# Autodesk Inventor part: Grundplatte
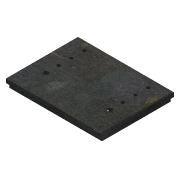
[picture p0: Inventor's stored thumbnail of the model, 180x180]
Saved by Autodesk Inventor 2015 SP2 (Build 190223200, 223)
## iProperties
Created: 2017-07
Material: St
Document SubType Name: Modeling
Designer: UR
Density: 7.85 g/cm^3
Appearance: Platte
Part Number: Grundplatte
Author: UR
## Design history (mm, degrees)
sketch "Skizze1"
  geometry: L1 (-60, 45)-(60, 45); L2 (60, 45)-(60, -45); L3 (60, -45)-(-60, -45); L4 (-60, -45)-(-60, 45); L5 (60, 45)-(-60, -45); 2 further points
  constraints: 10 end point, 2 parallel, 1 coincident, 1 horizontal, 1 midpoint, 1 perpendicular
  dimensions: "d0" = 120 distance of L2.end L3.end; "d1" = 90 distance of L3.end L1.start
extrude "Grundkörper" new body sketch "Skizze1" distance "d3" = 12; taper "d4" = 0 deg
node "Mittelebene xz"
node "Mittelebene yz"
sketch "Skizze für Bohrungen"
  geometry: L1 (0, 0)-(0, -15.692); L2 (60, 45)-(-60, 45) reference; 8 further points
  constraints: 4 symmetric about line, 3 vertical alignment, 2 end point, 1 vertical
  dimensions: "d5" = 80 distance of point (-40, -15) point (40, -15); "d6" = 16 distance of point (-40, 1) point (-40, -15); "d7" = 16 distance of point (-40, 17) point (-40, 1); "d8" = 16 distance of point (-40, 33) point (-40, 17); "d9" = 12 distance from line of point (-40, 33) L2
hole "Bohrung für Stanzmatrize" sketch "Skizze für Bohrungen" diameter "d10" = 6; stored, may be unused: countersink angle "d14" = 90 deg, drill point angle "d16" = 118 deg; dims "d11" = 6, "d12" = 4, "d13" = 2, "d15" = 8
hole "Durchgangsbohrung zur Oberplatte" sketch "Skizze für Bohrungen" diameter "d17" = 4.5; stored, may be unused: countersink angle "d21" = 90 deg, drill point angle "d23" = 118 deg; dims "d18" = 6, "d19" = 8, "d20" = 4.4, "d22" = 8
hole "Bohrung für Zylinderstifte" sketch "Skizze für Bohrungen" diameter "d24" = 4; stored, may be unused: countersink angle "d28" = 90 deg, drill point angle "d30" = 118 deg; dims "d25" = 6, "d26" = 8, "d27" = 4.4, "d29" = 8
sketch "Skizze3"
  geometry: L1 (60, 45)-(-60, 45) reference; L2 (-60, 45)-(-60, -45) reference; L3 (-60, -45)-(60, -45) reference; L4 (60, -45)-(60, 45) reference; L5 (0, 0)-(0, -20.468); L6 (-50, -40)-(50, -40); L7 (55, -35)-(55, -13); L8 (-55, -35)-(-55, -13); L9 (-26, 40)-(26, 40); L10 (-31, 35)-(-31, -8); L11 (31, 35)-(31, -8); L12 (-50, -8)-(-31, -8); L13 (31, -8)-(50, -8); C1 r 2 at (40, 17) reference; C2 r 2 at (-40, 17) reference; C3 r 4 at (-40, 33) reference; C4 r 4 at (40, 1) reference; C5 r 4 at (40, 33) reference; C6 r 4 at (-40, 1) reference; C7 r 3 at (40, -15) reference; C8 r 3 at (-40, -15) reference; A1 r 5 centre (-26, 35) between (-26, 40) and (-31, 35); A2 r 5 centre (-50, -13) between (-50, -8) and (-55, -13); A3 r 5 centre (-50, -35) between (-55, -35) and (-50, -40); A4 r 5 centre (26, 35) between (31, 35) and (26, 40); A5 r 5 centre (50, -13) between (55, -13) and (50, -8); A6 r 5 centre (50, -35) between (50, -40) and (55, -35)
  constraints: 18 end point, 12 point on circle, 9 tangent, 6 centre point, 6 perpendicular, 3 symmetric about line, 2 equal radius, 2 parallel, 2 vertical, 3 other
  dimensions: "d31" = 5 radius of A6; "d33" = 5 distance between parallel lines of L3 L6; "d34" = 5 distance between parallel lines of L9 L1; "d35" = 5 distance between parallel lines of L4 L7; "d36" = 5 distance edge to line of C3 L10; "d37" = 5 distance edge to line of C6 L12
extrude "Konfettitasche" cut sketch "Skizze3" distance "d38" = 10; taper "d39" = 0 deg
sketch "Skizze4"
  geometry: L1 (50, -40)-(-50, -40) reference; L2 (-55, -35)-(-55, -13) reference; L3 (-50, -8)-(-31, -8) reference; L4 (-31, -8)-(-31, 35) reference; L5 (-26, 40)-(26, 40) reference; L6 (31, 35)-(31, -8) reference; L7 (31, -8)-(50, -8) reference; L8 (55, -13)-(55, -35) reference; L9 (60, 45)-(-60, 45) reference; L10 (-60, 45)-(-60, -45) reference; L11 (-60, -45)-(60, -45) reference; L12 (60, -45)-(60, 45) reference; L13 (-60, 45)-(60, 45) reference; L14 (0, 45)-(0, 0); L15 (-60, -45)-(-60, 45) reference; L16 (60, 45)-(60, -45) reference; L17 (60, 0)-(-60, 0); L18 (-6, 6)-(6, 6); L19 (6, 6)-(6, -6); L20 (6, -6)-(-6, -6); L21 (-6, -6)-(-6, 6); C1 r 2 at (40, 17) reference; C2 r 2 at (-40, 17) reference; C3 r 4 at (-40, 33) reference; C4 r 4 at (40, 1) reference; C5 r 4 at (40, 33) reference; C6 r 4 at (-40, 1) reference; A1 r 5 centre (-50, -35) between (-55, -35) and (-50, -40) reference; A2 r 5 centre (-50, -13) between (-50, -8) and (-55, -13) reference; A3 r 5 centre (-26, 35) between (-26, 40) and (-31, 35) reference; A4 r 5 centre (26, 35) between (31, 35) and (26, 40) reference; A5 r 5 centre (50, -13) between (55, -13) and (50, -8) reference; A6 r 5 centre (50, -35) between (50, -40) and (55, -35) reference
  constraints: 12 end point, 4 perpendicular, 3 midpoint, 2 parallel, 1 horizontal, 2 other
  dimensions: "d40" = 12 distance between parallel lines of L19 L21
extrude "Nupsi für Magnet" join sketch "Skizze4" distance "d41" = 9; taper "d42" = 0 deg
sketch "Skizze5"
  geometry: L1 (6, 6)-(-6, 6) reference; L2 (-6, 6)-(-6, -6) reference; L3 (-6, -6)-(6, -6) reference; L4 (6, -6)-(6, 6) reference; L5 (-6, 6)-(-6, -6) reference; L6 (-6, 0)-(6, 0); L7 (6, 6)-(6, -6) reference; 2 further points
  constraints: 3 midpoint, 2 end point
hole "Bohrung für Magnet" sketch "Skizze5" at (0, 0) diameter "d43" = 8; stored, may be unused: countersink angle "d47" = 90 deg, drill point angle "d49" = 118 deg; dims "d44" = 6, "d45" = 8, "d46" = 4.4, "d48" = 5
sketch "Skizze6"
  geometry: L1 (50, -40)-(-50, -40) reference; L2 (-55, -35)-(-55, -13) reference; L3 (-50, -8)-(-31, -8) reference; L4 (-31, -8)-(-31, 35) reference; L5 (-26, 40)-(26, 40) reference; L6 (31, 35)-(31, -8) reference; L7 (31, -8)-(50, -8) reference; L8 (55, -13)-(55, -35) reference; L9 (60, 45)-(-60, 45) reference; L10 (-60, 45)-(-60, -45) reference; L11 (-60, -45)-(60, -45) reference; L12 (60, -45)-(60, 45) reference; L13 (-58, -43)-(-58, 43); L14 (-58, 43)-(58, 43); L15 (58, 43)-(58, -43); L16 (58, -43)-(-58, -43); C1 r 2 at (40, 17) reference; C2 r 2 at (-40, 17) reference; C3 r 4 at (-40, 33) reference; C4 r 4 at (40, 1) reference; C5 r 4 at (40, 33) reference; C6 r 4 at (-40, 1) reference; A1 r 5 centre (-50, -35) between (-55, -35) and (-50, -40) reference; A2 r 5 centre (-50, -13) between (-50, -8) and (-55, -13) reference; A3 r 5 centre (-26, 35) between (-26, 40) and (-31, 35) reference; A4 r 5 centre (26, 35) between (31, 35) and (26, 40) reference; A5 r 5 centre (50, -13) between (55, -13) and (50, -8) reference; A6 r 5 centre (50, -35) between (50, -40) and (55, -35) reference; 1 further point
  constraints: 8 end point, 3 other
  dimensions: "d50" = 2 distance between parallel lines of L11 L16
extrude "Umlaufender Absatz für Fußplatte" cut sketch "Skizze6" distance "d51" = 6; taper "d52" = 0 deg
chamfer "Umlaufender Absatz" distance "d58" = 1; stored, may be unused: second distance "d59" = 2, angle "d60" = 45 deg
sketch "Skizze7"
  geometry: L1 (-12, 2)-(-12, 88) reference; L2 (-6, 0)-(0, 0) reference; L3 (-12, 32)-(-12, 10) reference; L4 (-6.8, 17.1)-(-12, 17.1); L5 (-12, 17.1)-(-12, 6.9); L6 (-12, 6.9)-(-6.8, 6.9); L7 (-6.8, 6.9)-(-6.8, 17.1); L8 (-6.8, 12)-(-20.864, 12); 1 further point
  constraints: 10 end point, 2 parallel, 2 perpendicular, 1 horizontal, 1 midpoint, 1 point on line
  dimensions: "d54" = 10.2 distance between parallel lines of L6 L4; "d55" = 5.2 distance of L5.end L6.end; "d64" = 12 distance between parallel lines of L2 L8
extrude "Durchbruch für Anschlag" cut sketch "Skizze7" distance "d56" = 10; taper "d57" = 0 deg
chamfer "Außenkanten" distance "d61" = 1; stored, may be unused: second distance "d62" = 2, angle "d63" = 45 deg
node "Volumenkörper1"
node "Projizierte Kontur1"
node "Projizierte Kontur2"
node "Projizierte Kontur3"
node "Projizierte Kontur4"
